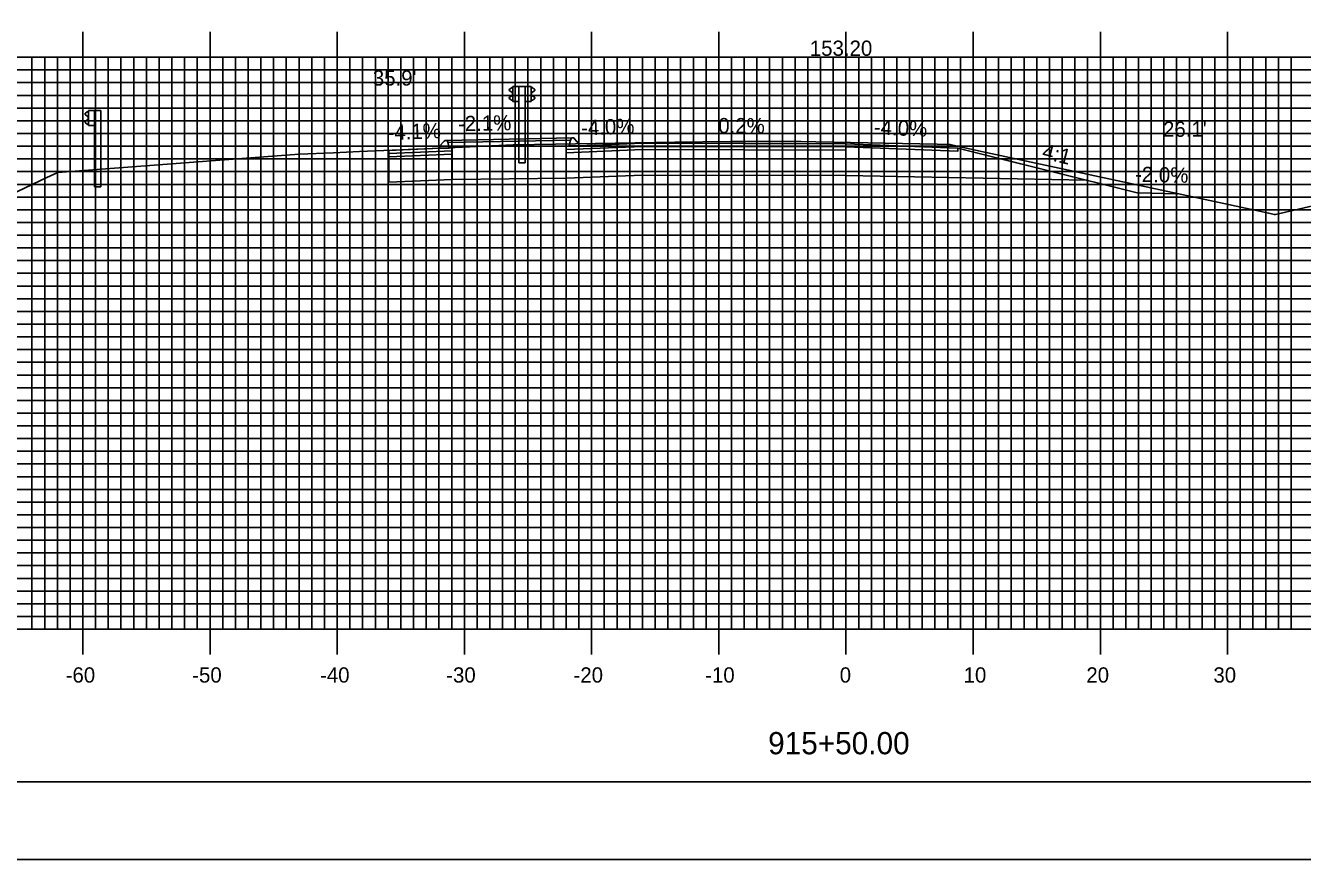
# Model space of a CAD drawing. Extents: x 861045 to 861388, y 364765 to 364985.
# Drawn here: x 861146.4 to 861246.8, y 364765.2 to 364830.8 of the extents above; entities that cross this region are included whole.
import ezdxf

# ---------------------------------------------------------------- set-up
doc = ezdxf.new("R2010")
doc.units = 0
for name, color, linetype in [('ANNOTATION', 7, 'Continuous'), ('BORDER', 7, 'Continuous'), ('D_Curb_Type_3M2_Lt', 7, 'Continuous'), ('D_Curb_Type_3M2_Rt', 7, 'Continuous'), ('D_Roadway_Centerline', 7, 'Continuous'), ('D_Roadway_Centerline_Text', 7, 'Continuous'), ('D_Roadway_Edge_Shoulder', 7, 'Continuous'), ('D_Roadway_Edge_TW', 7, 'Continuous'), ('D_Roadway_FinishedGrade', 7, 'Continuous'), ('D_Roadway_Pavement', 7, 'Continuous'), ('D_Roadway_SubGrade', 7, 'Continuous'), ('D_Text_Standard', 7, 'Continuous'), ('H_V ANNOTATION', 7, 'Continuous'), ('M_Guardrail', 7, 'Continuous'), ('M_Roadway_Centerline', 7, 'Continuous'), ('MAJOR', 7, 'Continuous'), ('MINOR', 7, 'Continuous'), ('PLOT BOUNDARY', 7, 'Continuous'), ('S_Roadway_Centerline', 7, 'Continuous')]:
    doc.layers.add(name, color=color, linetype=linetype)

msp = doc.modelspace()

# ---------------------------------------------------------------- linework, layer by layer
at = {"layer": 'BORDER'}
msp.add_lwpolyline([(861061.33, 364771.3), (861381.33, 364771.3), (861381.33, 364981.3), (861061.33, 364981.3)], close=True, dxfattribs=at)
at = {"layer": 'D_Curb_Type_3M2_Lt'}
for p, q in [((861189.28, 364821.83), (861189.17, 364821.33)), ((861189.17, 364821.33), (861189.92, 364821.33)), ((861189.42, 364821.95), (861189.42, 364821.95)), ((861189.92, 364821.5), (861189.57, 364821.9)), ((861189.92, 364821.33), (861189.92, 364821.5))]:
    msp.add_line(p, q, dxfattribs=at)
msp.add_arc((861189.45, 364821.79), 0.167, 41.387, 167.6648, dxfattribs=at)
at = {"layer": 'D_Curb_Type_3M2_Rt'}
for p, q in [((861178.98, 364821.3), (861179.34, 364821.71)), ((861178.98, 364821.14), (861178.98, 364821.3)), ((861179.63, 364821.63), (861179.73, 364821.14)), ((861179.73, 364821.14), (861178.98, 364821.14))]:
    msp.add_line(p, q, dxfattribs=at)
msp.add_arc((861179.46, 364821.6), 0.167, 12.3352, 138.613, dxfattribs=at)
at = {"layer": 'D_Roadway_Centerline'}
msp.add_line((861233.82, 364817.63), (861236.99, 364817.56), dxfattribs=at)
for points in [[(861189.92, 364821.33), (861190.08, 364821.34), (861194.92, 364821.53), (861194.93, 364821.53), (861203.02, 364821.52), (861210.92, 364821.5), (861210.93, 364821.5), (861210.93, 364821.5), (861219.72, 364821.15), (861219.72, 364821.15), (861233.82, 364817.63)], [(861174.98, 364820.97), (861178.97, 364821.14)]]:
    msp.add_lwpolyline(points, dxfattribs=at)
at = {"layer": 'D_Roadway_Edge_Shoulder'}
for points in [[(861194.93, 364821.53), (861189.92, 364821.33), (861188.93, 364821.29), (861188.93, 364821.04), (861194.93, 364821.28)], [(861210.93, 364821.5), (861219.72, 364821.15), (861219.72, 364820.9), (861210.93, 364821.25)], [(861174.98, 364820.97), (861178.98, 364821.14), (861179.98, 364821.18), (861179.98, 364820.93), (861174.98, 364820.72)]]:
    msp.add_lwpolyline(points, close=True, dxfattribs=at)
at = {"layer": 'D_Roadway_Edge_TW'}
msp.add_lwpolyline([(861194.93, 364821.53), (861210.93, 364821.5), (861210.93, 364821.25), (861194.93, 364821.28)], close=True, dxfattribs=at)
at = {"layer": 'D_Roadway_FinishedGrade'}
msp.add_lwpolyline([(861179.5, 364821.76), (861189.4, 364821.95)], dxfattribs=at)
at = {"layer": 'D_Roadway_Pavement'}
for points in [[(861194.93, 364821.28), (861188.93, 364821.04), (861188.93, 364820.79), (861194.93, 364821.03)], [(861194.93, 364821.28), (861210.93, 364821.25), (861210.93, 364821), (861194.93, 364821.03)], [(861174.98, 364820.72), (861179.98, 364820.93), (861179.98, 364820.68), (861174.98, 364820.47)]]:
    msp.add_lwpolyline(points, close=True, dxfattribs=at)
msp.add_lwpolyline([(861210.93, 364821.25), (861210.93, 364821)], dxfattribs=at)
msp.add_lwpolyline([(861210.93, 364821.25), (861210.93, 364821)], dxfattribs=at)
msp.add_lwpolyline([(861210.93, 364821.25), (861210.93, 364821)], dxfattribs=at)
msp.add_lwpolyline([(861210.93, 364821.25), (861210.93, 364821)], dxfattribs=at)
at = {"layer": 'D_Roadway_SubGrade'}
for points in [[(861179.98, 364821.18), (861179.98, 364818.68), (861188.93, 364818.79), (861188.93, 364820.79), (861188.93, 364821.04), (861188.93, 364821.29), (861189.17, 364821.3), (861189.27, 364821.78), (861179.63, 364821.59), (861179.73, 364821.17)], [(861210.93, 364821), (861210.93, 364821.25), (861219.72, 364820.9), (861219.72, 364821.15), (861229.82, 364818.63), (861210.93, 364819)], [(861174.98, 364820.47), (861179.98, 364820.68), (861179.98, 364820.93), (861179.98, 364818.68), (861174.98, 364818.47)], [(861194.93, 364821.03), (861188.93, 364820.79), (861188.93, 364821.04), (861188.93, 364818.79), (861194.93, 364819.03)], [(861194.93, 364821.03), (861210.93, 364821), (861210.93, 364819), (861194.93, 364819.03)]]:
    msp.add_lwpolyline(points, close=True, dxfattribs=at)
at = {"layer": 'M_Guardrail'}
for p, q in [((861184.63, 364825.9), (861184.49, 364825.8)), ((861184.49, 364825.66), (861184.68, 364825.52)), ((861184.68, 364825.3), (861184.49, 364825.17)), ((861184.73, 364825.92), (861184.65, 364825.91)), ((861184.72, 364825.46), (861184.72, 364825.37)), ((861184.73, 364826), (861185.22, 364826)), ((861184.73, 364824.83), (861184.73, 364826)), ((861185.21, 364826), (861185.21, 364820)), ((861185.7, 364826), (861185.21, 364826)), ((861185.22, 364826), (861185.71, 364826)), ((861185.22, 364826), (861185.22, 364824.83)), ((861186.19, 364826), (861185.7, 364826)), ((861185.7, 364826), (861185.7, 364824.83)), ((861185.71, 364826), (861185.71, 364820)), ((861186.19, 364824.83), (861186.19, 364826)), ((861186.19, 364825.92), (861186.27, 364825.91)), ((861186.2, 364825.46), (861186.2, 364825.37)), ((861186.43, 364825.66), (861186.23, 364825.52)), ((861186.23, 364825.3), (861186.43, 364825.17)), ((861186.29, 364825.9), (861186.43, 364825.8)), ((861184.49, 364825.02), (861184.63, 364824.92)), ((861184.65, 364824.92), (861184.73, 364824.9)), ((861185.22, 364824.83), (861184.73, 364824.83)), ((861185.22, 364820), (861185.22, 364824.83)), ((861185.7, 364820), (861185.7, 364824.83)), ((861185.7, 364824.83), (861186.19, 364824.83)), ((861186.27, 364824.92), (861186.19, 364824.9)), ((861186.43, 364825.02), (861186.29, 364824.92)), ((861151.27, 364824.01), (861151.13, 364823.91)), ((861151.13, 364823.76), (861151.33, 364823.63)), ((861151.33, 364823.41), (861151.13, 364823.27)), ((861151.37, 364824.03), (861151.29, 364824.01)), ((861151.36, 364823.56), (861151.36, 364823.47)), ((861151.37, 364824.1), (861151.86, 364824.1)), ((861151.37, 364822.93), (861151.37, 364824.1)), ((861151.86, 364824.1), (861152.35, 364824.1)), ((861151.86, 364824.1), (861151.86, 364822.93)), ((861152.35, 364824.1), (861152.35, 364818.1)), ((861151.13, 364823.13), (861151.27, 364823.03)), ((861151.29, 364823.02), (861151.37, 364823.01)), ((861151.86, 364822.93), (861151.37, 364822.93)), ((861151.86, 364818.1), (861151.86, 364822.93)), ((861185.7, 364820), (861185.21, 364820)), ((861185.22, 364820), (861185.71, 364820)), ((861151.86, 364818.1), (861152.35, 364818.1))]:
    msp.add_line(p, q, dxfattribs=at)
for centre, major_axis, start_param, end_param in [((861184.54, 364825.73), (-0.0877, 0), 5.323254, 7.243116), ((861184.65, 364825.87), (-0.0417, 0), 4.886922, 5.323254), ((861184.64, 364825.46), (0.0789, 0), 0, 0.959931), ((861184.64, 364825.37), (0.0789, 0), 5.323254, 6.283185), ((861186.28, 364825.46), (-0.0789, 0), 5.323254, 6.283185), ((861186.28, 364825.37), (-0.0789, 0), 6.283185, 7.243116), ((861186.26, 364825.87), (0.0417, 0), 0.959931, 1.396263), ((861186.38, 364825.73), (0.0877, 0), 5.323254, 7.243116), ((861184.54, 364825.1), (-0.0877, 0), 5.323254, 7.243116), ((861184.65, 364824.96), (-0.0417, 0), 0.959931, 1.396263), ((861186.26, 364824.96), (0.0417, 0), 4.886922, 5.323254), ((861186.38, 364825.09), (0.0877, 0), 5.323254, 7.243116), ((861151.18, 364823.83), (-0.0877, 0), 5.323254, 7.243116), ((861151.18, 364823.2), (-0.0877, 0), 5.323254, 7.243116), ((861151.3, 364823.97), (-0.0417, 0), 4.886922, 5.323254), ((861151.28, 364823.56), (0.0789, 0), 0, 0.959931), ((861151.28, 364823.47), (0.0789, 0), 5.323254, 6.283185), ((861151.3, 364823.06), (-0.0417, 0), 0.959931, 1.396263)]:
    msp.add_ellipse(centre, major_axis=major_axis, ratio=0.995501, start_param=start_param, end_param=end_param, dxfattribs=at)
at = {"layer": 'MAJOR'}
for p, q in [((861150.93, 364830.31), (861150.93, 364828.3)), ((861160.93, 364830.31), (861160.93, 364828.3)), ((861170.93, 364830.31), (861170.93, 364828.3)), ((861180.93, 364830.31), (861180.93, 364828.3)), ((861190.93, 364830.31), (861190.93, 364828.3)), ((861200.93, 364830.31), (861200.93, 364828.3)), ((861210.93, 364830.31), (861210.93, 364828.3)), ((861220.93, 364830.31), (861220.93, 364828.3)), ((861230.93, 364830.31), (861230.93, 364828.3)), ((861240.93, 364830.31), (861240.93, 364828.3)), ((861070.93, 364828.3), (861350.93, 364828.3)), ((861070.93, 364828.3), (861350.93, 364828.3)), ((861150.93, 364783.3), (861150.93, 364828.3)), ((861160.93, 364783.3), (861160.93, 364828.3)), ((861170.93, 364783.3), (861170.93, 364828.3)), ((861180.93, 364783.3), (861180.93, 364828.3)), ((861190.93, 364783.3), (861190.93, 364828.3)), ((861200.93, 364783.3), (861200.93, 364828.3)), ((861210.93, 364783.3), (861210.93, 364828.3)), ((861220.93, 364783.3), (861220.93, 364828.3)), ((861230.93, 364783.3), (861230.93, 364828.3)), ((861240.93, 364783.3), (861240.93, 364828.3)), ((861070.93, 364823.3), (861350.93, 364823.3)), ((861070.93, 364818.3), (861350.93, 364818.3)), ((861070.93, 364813.3), (861350.93, 364813.3)), ((861070.93, 364808.3), (861350.93, 364808.3)), ((861070.93, 364803.3), (861350.93, 364803.3)), ((861070.93, 364798.3), (861350.93, 364798.3)), ((861070.93, 364793.3), (861350.93, 364793.3)), ((861070.93, 364788.3), (861350.93, 364788.3)), ((861070.93, 364783.3), (861350.93, 364783.3)), ((861070.93, 364783.3), (861350.93, 364783.3)), ((861150.93, 364781.3), (861150.93, 364783.3)), ((861160.93, 364781.3), (861160.93, 364783.3)), ((861170.93, 364781.3), (861170.93, 364783.3)), ((861180.93, 364781.3), (861180.93, 364783.3)), ((861190.93, 364781.3), (861190.93, 364783.3)), ((861200.93, 364781.3), (861200.93, 364783.3)), ((861210.93, 364781.3), (861210.93, 364783.3)), ((861220.93, 364781.3), (861220.93, 364783.3)), ((861230.93, 364781.3), (861230.93, 364783.3)), ((861240.93, 364781.3), (861240.93, 364783.3))]:
    msp.add_line(p, q, dxfattribs=at)
at = {"layer": 'MINOR'}
for p, q in [((861146.93, 364783.3), (861146.93, 364828.3)), ((861147.93, 364783.3), (861147.93, 364828.3)), ((861148.93, 364783.3), (861148.93, 364828.3)), ((861149.93, 364783.3), (861149.93, 364828.3)), ((861151.93, 364783.3), (861151.93, 364828.3)), ((861152.93, 364783.3), (861152.93, 364828.3)), ((861153.93, 364783.3), (861153.93, 364828.3)), ((861154.93, 364783.3), (861154.93, 364828.3)), ((861155.93, 364783.3), (861155.93, 364828.3)), ((861156.93, 364783.3), (861156.93, 364828.3)), ((861157.93, 364783.3), (861157.93, 364828.3)), ((861158.93, 364783.3), (861158.93, 364828.3)), ((861159.93, 364783.3), (861159.93, 364828.3)), ((861161.93, 364783.3), (861161.93, 364828.3)), ((861162.93, 364783.3), (861162.93, 364828.3)), ((861163.93, 364783.3), (861163.93, 364828.3)), ((861164.93, 364783.3), (861164.93, 364828.3)), ((861165.93, 364783.3), (861165.93, 364828.3)), ((861166.93, 364783.3), (861166.93, 364828.3)), ((861167.93, 364783.3), (861167.93, 364828.3)), ((861168.93, 364783.3), (861168.93, 364828.3)), ((861169.93, 364783.3), (861169.93, 364828.3)), ((861171.93, 364783.3), (861171.93, 364828.3)), ((861172.93, 364783.3), (861172.93, 364828.3)), ((861173.93, 364783.3), (861173.93, 364828.3)), ((861174.93, 364783.3), (861174.93, 364828.3)), ((861175.93, 364783.3), (861175.93, 364828.3)), ((861176.93, 364783.3), (861176.93, 364828.3)), ((861177.93, 364783.3), (861177.93, 364828.3)), ((861178.93, 364783.3), (861178.93, 364828.3)), ((861179.93, 364783.3), (861179.93, 364828.3)), ((861181.93, 364783.3), (861181.93, 364828.3)), ((861182.93, 364783.3), (861182.93, 364828.3)), ((861183.93, 364783.3), (861183.93, 364828.3)), ((861184.93, 364783.3), (861184.93, 364828.3)), ((861185.93, 364783.3), (861185.93, 364828.3)), ((861186.93, 364783.3), (861186.93, 364828.3)), ((861187.93, 364783.3), (861187.93, 364828.3)), ((861188.93, 364783.3), (861188.93, 364828.3)), ((861189.93, 364783.3), (861189.93, 364828.3)), ((861191.93, 364783.3), (861191.93, 364828.3)), ((861192.93, 364783.3), (861192.93, 364828.3)), ((861193.93, 364783.3), (861193.93, 364828.3)), ((861194.93, 364783.3), (861194.93, 364828.3)), ((861195.93, 364783.3), (861195.93, 364828.3)), ((861196.93, 364783.3), (861196.93, 364828.3)), ((861197.93, 364783.3), (861197.93, 364828.3)), ((861198.93, 364783.3), (861198.93, 364828.3)), ((861199.93, 364783.3), (861199.93, 364828.3)), ((861201.93, 364783.3), (861201.93, 364828.3)), ((861202.93, 364783.3), (861202.93, 364828.3)), ((861203.93, 364783.3), (861203.93, 364828.3)), ((861204.93, 364783.3), (861204.93, 364828.3)), ((861205.93, 364783.3), (861205.93, 364828.3)), ((861206.93, 364783.3), (861206.93, 364828.3)), ((861207.93, 364783.3), (861207.93, 364828.3)), ((861208.93, 364783.3), (861208.93, 364828.3)), ((861209.93, 364783.3), (861209.93, 364828.3)), ((861211.93, 364783.3), (861211.93, 364828.3)), ((861212.93, 364783.3), (861212.93, 364828.3)), ((861213.93, 364783.3), (861213.93, 364828.3)), ((861214.93, 364783.3), (861214.93, 364828.3)), ((861215.93, 364783.3), (861215.93, 364828.3)), ((861216.93, 364783.3), (861216.93, 364828.3)), ((861217.93, 364783.3), (861217.93, 364828.3)), ((861218.93, 364783.3), (861218.93, 364828.3)), ((861219.93, 364783.3), (861219.93, 364828.3)), ((861221.93, 364783.3), (861221.93, 364828.3)), ((861222.93, 364783.3), (861222.93, 364828.3)), ((861223.93, 364783.3), (861223.93, 364828.3)), ((861224.93, 364783.3), (861224.93, 364828.3)), ((861225.93, 364783.3), (861225.93, 364828.3)), ((861226.93, 364783.3), (861226.93, 364828.3)), ((861227.93, 364783.3), (861227.93, 364828.3)), ((861228.93, 364783.3), (861228.93, 364828.3)), ((861229.93, 364783.3), (861229.93, 364828.3)), ((861231.93, 364783.3), (861231.93, 364828.3)), ((861232.93, 364783.3), (861232.93, 364828.3)), ((861233.93, 364783.3), (861233.93, 364828.3)), ((861234.93, 364783.3), (861234.93, 364828.3)), ((861235.93, 364783.3), (861235.93, 364828.3)), ((861236.93, 364783.3), (861236.93, 364828.3)), ((861237.93, 364783.3), (861237.93, 364828.3)), ((861238.93, 364783.3), (861238.93, 364828.3)), ((861239.93, 364783.3), (861239.93, 364828.3)), ((861241.93, 364783.3), (861241.93, 364828.3)), ((861242.93, 364783.3), (861242.93, 364828.3)), ((861243.93, 364783.3), (861243.93, 364828.3)), ((861244.93, 364783.3), (861244.93, 364828.3)), ((861245.93, 364783.3), (861245.93, 364828.3)), ((861070.93, 364827.3), (861350.93, 364827.3)), ((861070.93, 364826.3), (861350.93, 364826.3)), ((861070.93, 364825.3), (861350.93, 364825.3)), ((861070.93, 364824.3), (861350.93, 364824.3)), ((861070.93, 364822.3), (861350.93, 364822.3)), ((861070.93, 364821.3), (861350.93, 364821.3)), ((861070.93, 364820.3), (861350.93, 364820.3)), ((861070.93, 364819.3), (861350.93, 364819.3)), ((861070.93, 364817.3), (861350.93, 364817.3)), ((861070.93, 364816.3), (861350.93, 364816.3)), ((861070.93, 364815.3), (861350.93, 364815.3)), ((861070.93, 364814.3), (861350.93, 364814.3)), ((861070.93, 364812.3), (861350.93, 364812.3)), ((861070.93, 364811.3), (861350.93, 364811.3)), ((861070.93, 364810.3), (861350.93, 364810.3)), ((861070.93, 364809.3), (861350.93, 364809.3)), ((861070.93, 364807.3), (861350.93, 364807.3)), ((861070.93, 364806.3), (861350.93, 364806.3)), ((861070.93, 364805.3), (861350.93, 364805.3)), ((861070.93, 364804.3), (861350.93, 364804.3)), ((861070.93, 364802.3), (861350.93, 364802.3)), ((861070.93, 364801.3), (861350.93, 364801.3)), ((861070.93, 364800.3), (861350.93, 364800.3)), ((861070.93, 364799.3), (861350.93, 364799.3)), ((861070.93, 364797.3), (861350.93, 364797.3)), ((861070.93, 364796.3), (861350.93, 364796.3)), ((861070.93, 364795.3), (861350.93, 364795.3)), ((861070.93, 364794.3), (861350.93, 364794.3)), ((861070.93, 364792.3), (861350.93, 364792.3)), ((861070.93, 364791.3), (861350.93, 364791.3)), ((861070.93, 364790.3), (861350.93, 364790.3)), ((861070.93, 364789.3), (861350.93, 364789.3)), ((861070.93, 364787.3), (861350.93, 364787.3)), ((861070.93, 364786.3), (861350.93, 364786.3)), ((861070.93, 364785.3), (861350.93, 364785.3)), ((861070.93, 364784.3), (861350.93, 364784.3))]:
    msp.add_line(p, q, dxfattribs=at)
at = {"layer": 'PLOT BOUNDARY'}
msp.add_lwpolyline([(861045.14, 364765.18), (861385.14, 364765.18), (861385.14, 364985.18), (861045.14, 364985.18)], close=True, dxfattribs=at)
at = {"layer": 'S_Roadway_Centerline'}
msp.add_lwpolyline([(861144.02, 364816.91), (861148.1, 364818.85), (861148.96, 364819.24), (861152.74, 364819.51), (861166.88, 364820.59), (861167.95, 364820.68), (861170.63, 364820.78), (861172.67, 364820.88), (861179.08, 364821.14), (861184.77, 364821.42), (861188.08, 364821.47), (861197.48, 364821.61), (861201.85, 364821.67), (861202.12, 364821.68), (861207.42, 364821.67), (861208.57, 364821.65), (861218.1, 364821.46), (861219.1, 364821.44), (861221.95, 364820.8), (861244.17, 364816.02), (861244.59, 364815.93), (861244.71, 364815.93), (861247.63, 364816.62)], dxfattribs=at)

# ---------------------------------------------------------------- texts
at = {"layer": 'ANNOTATION'}
for s, rotation, p in [('-2.1%', 1.1873, (861180.44, 364822.47)), ('-4.0%', 2.2904, (861190.13, 364822.14)), ('0.2%', 359.9033, (861200.89, 364822.32)), ('-4.0%', 357.7076, (861213.11, 364822.22)), ('-4.1%', 2.3586, (861174.91, 364821.77)), ('4:1', 345.9654, (861226.28, 364820.37)), ('-2.0%', 358.8634, (861233.65, 364818.5))]:
    msp.add_text(s, height=1.2, rotation=rotation, dxfattribs=at).set_placement(p)
at = {"layer": 'D_Roadway_Centerline_Text'}
msp.add_text('153.20', height=1.2, dxfattribs=at).set_placement((861208.09, 364828.41))
at = {"layer": 'D_Text_Standard'}
for s, p in [("35.9'", (861173.73, 364826.07)), ("26.1'", (861235.86, 364822.04))]:
    msp.add_text(s, height=1.2, dxfattribs=at).set_placement(p)
at = {"layer": 'H_V ANNOTATION'}
for s, height, p in [('-60', 1.2, (861149.58, 364779.1)), ('-50', 1.2, (861159.53, 364779.1)), ('-40', 1.2, (861169.58, 364779.1)), ('-30', 1.2, (861179.5, 364779.1)), ('-20', 1.2, (861189.51, 364779.1)), ('-10', 1.2, (861199.86, 364779.1)), ('0', 1.2, (861210.44, 364779.1)), ('10', 1.2, (861220.18, 364779.1)), ('20', 1.2, (861229.83, 364779.1)), ('30', 1.2, (861239.82, 364779.1)), ('915+50.00', 1.75, (861204.81, 364773.46))]:
    msp.add_text(s, height=height, dxfattribs=at).set_placement(p)
at = {"layer": 'M_Roadway_Centerline'}
for s, p in [('C', (861202.12, 364821.68)), ('L', (861202.12, 364821.67)), ('C', (861167.94, 364820.68)), ('L', (861167.95, 364820.67))]:
    msp.add_text(s, height=0.0146, dxfattribs=at).set_placement(p)

doc.saveas('drawing.dxf')
